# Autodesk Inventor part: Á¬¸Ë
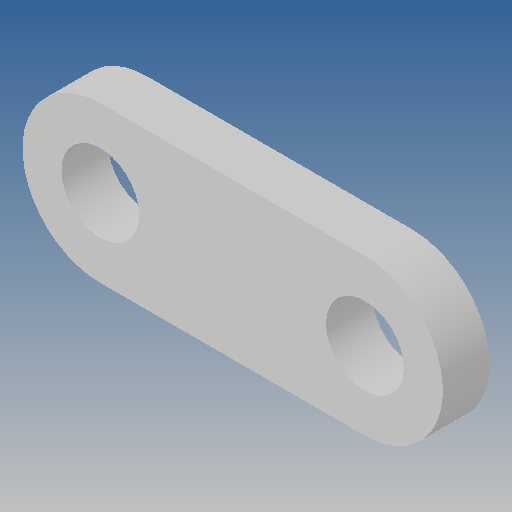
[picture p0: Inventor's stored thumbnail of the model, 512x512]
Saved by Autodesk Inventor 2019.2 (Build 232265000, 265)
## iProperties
Created: 2013-07
Part Number: Á¬¸Ë
Material: Ogólny
Document SubType Name: Modeling
Designer: CADENGINEERING4
Density: 1 g/cm^3
Appearance: Domyślna
Author: CADENGINEERING4
Revision Number: ÈÎºÎ
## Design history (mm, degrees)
feature "À­Éì1"
node "Bryła1"
